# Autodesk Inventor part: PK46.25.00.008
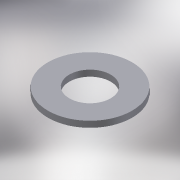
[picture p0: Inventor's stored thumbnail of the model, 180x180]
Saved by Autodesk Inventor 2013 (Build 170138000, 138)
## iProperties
Created: 2005-05
Part Number: PK46.25.00.008
Material: Steel, Mild
Document SubType Name: Modeling
Designer: PVitaliy
Manufacturer: Standard
Standards Organization: Custom
Density: 7.86 g/cm^3
Mass: 453.56 g
Surface Area: 185.48 cm^2
Volume: 57.7048 cm^3
Author: PVitaliy
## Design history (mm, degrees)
sketch "Эскиз2"
  geometry: C1 r 55 at (0, 0); C2 r 27 at (0, 0)
  constraints: 2 centre point, 1 coincident, 1 other
  dimensions: "d0" = 110 diameter of C1; "d1" = 54 diameter of C2
extrude "Выдавливание1" new body sketch "Эскиз2" distance "d2" = 8; taper "d3" = 0 deg
body "Solid1"
